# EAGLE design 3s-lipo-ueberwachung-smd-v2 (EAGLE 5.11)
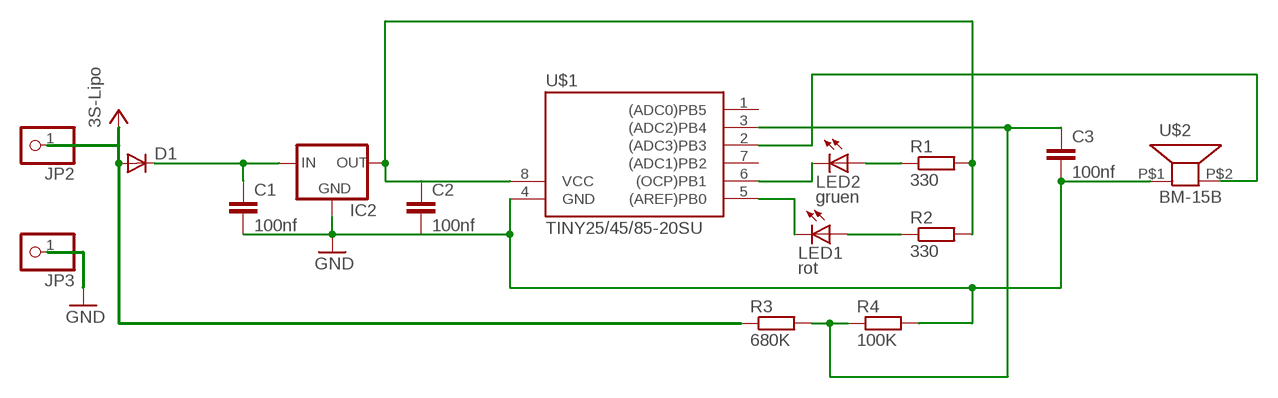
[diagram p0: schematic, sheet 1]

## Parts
C1  100nf  C-EUC0603  [C0603]
C2  100nf  C-EUC0603  [C0603]
C3  100nf  C-EUC0603  [C0603]
D1  DIODE-MINIMELF  [MINIMELF]
IC2  78LXX  [78LXX]
JP2  PINHD-1X1  [1X01]
JP3  PINHD-1X1  [1X01]
LED1  rot  LED3MM  [LED3MM]
LED2  gruen  LED3MM  [LED3MM]
R1  330  R-EU_R0603  [R0603]
R2  330  R-EU_R0603  [R0603]
R3  680K  R-EU_R0603  [R0603]
R4  100K  R-EU_R0603  [R0603]
U$1  TINY25/45/85-20SU  [SOIC8]
U$2  BM-15B  [BM-15B]

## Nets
GND: C1.2 C2.2 C3.2 IC2.GND JP3.1 R4.2 U$1.4(GND) U$2.P$1
N$1: LED2.K(C) U$1.6((OCP)PB1)
N$2: U$1.2((ADC3)PB3) U$2.P$2
N$4: LED1.K(C) U$1.5((AREF)PB0)
N$5: LED2.A R1.1
N$6: LED1.A R2.1
N$7: C1.1 D1.C IC2.IN
N$8: C2.1 IC2.OUT R1.2 R2.2 U$1.8(VCC)
N$9: C3.1 R3.2 R4.1 U$1.3((ADC2)PB4)
VCC: D1.A JP2.1 R3.1 ; supply symbol labelled 3S-Lipo
Unconnected: U$1.1((ADC0)PB5) U$1.7((ADC1)PB2)

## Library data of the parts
C1-C3 = rcl:C-EU: CAPACITOR, European symbol
D1 = diode:DIODE-: DIODE
IC2 = v-reg:78LXX: VOLTAGE REGULATOR
JP2 JP3 = pinhead:PINHD-1X1: PIN HEADER
LED1 LED2 = led:LED: LED
R1-R4 = rcl:R-EU_: RESISTOR, European symbol
U$1 = avr-6:TINY25/45/85
U$2 = buzzer:BM-15B

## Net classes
0 default: width 0.381 mm, clearance 0.381 mm

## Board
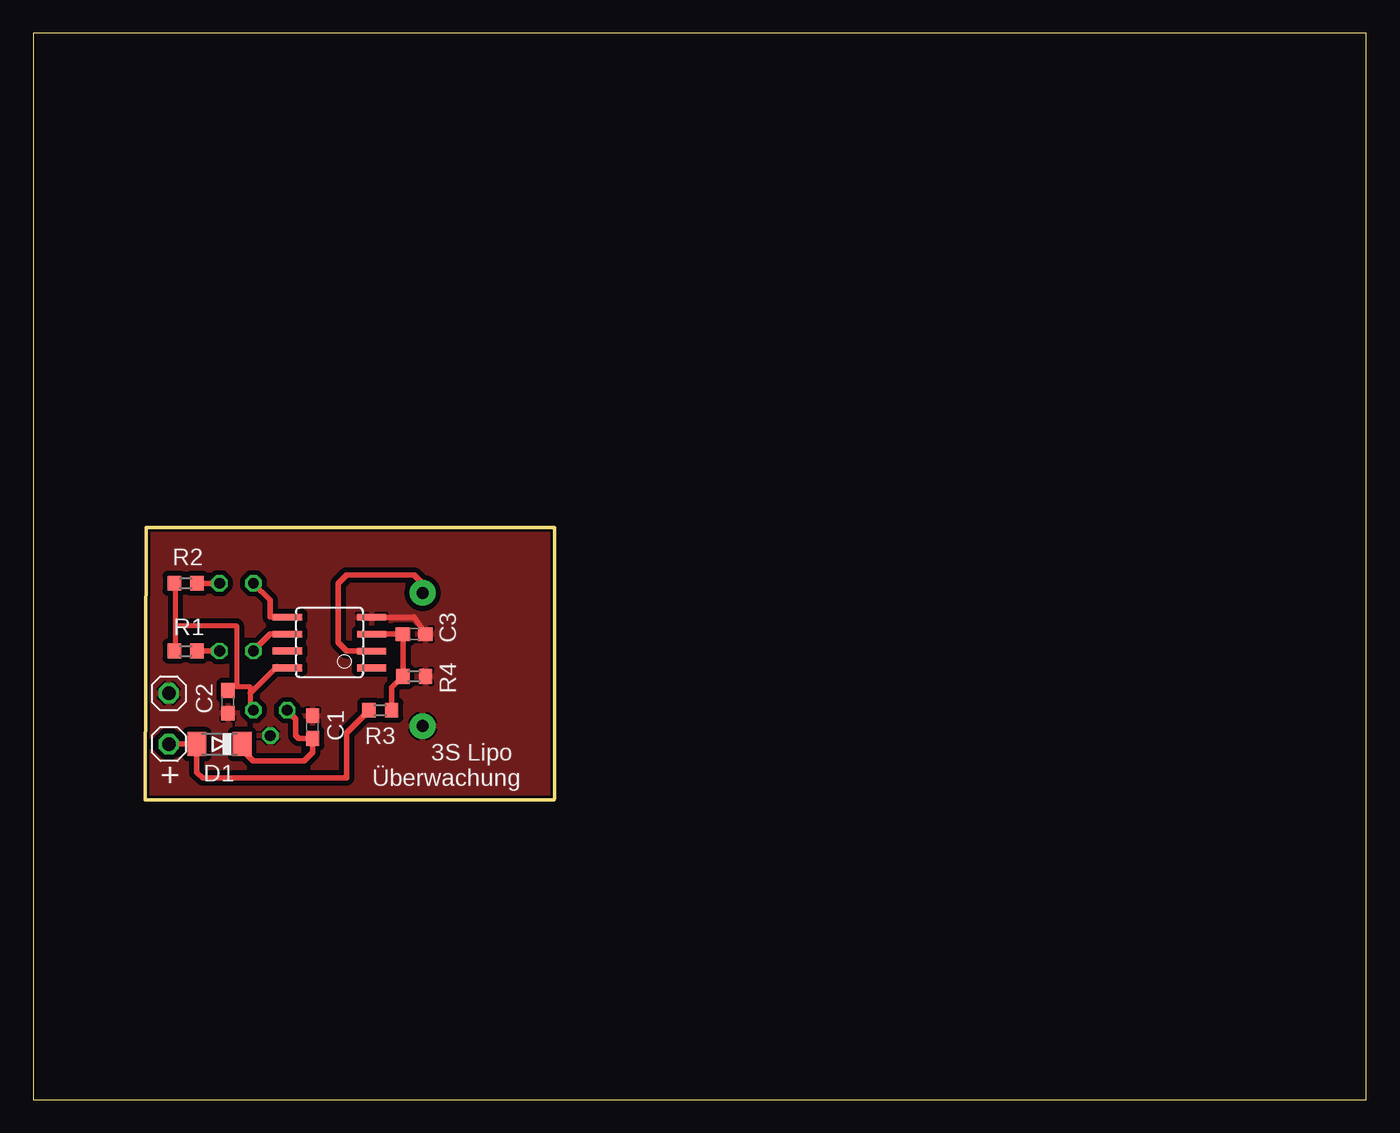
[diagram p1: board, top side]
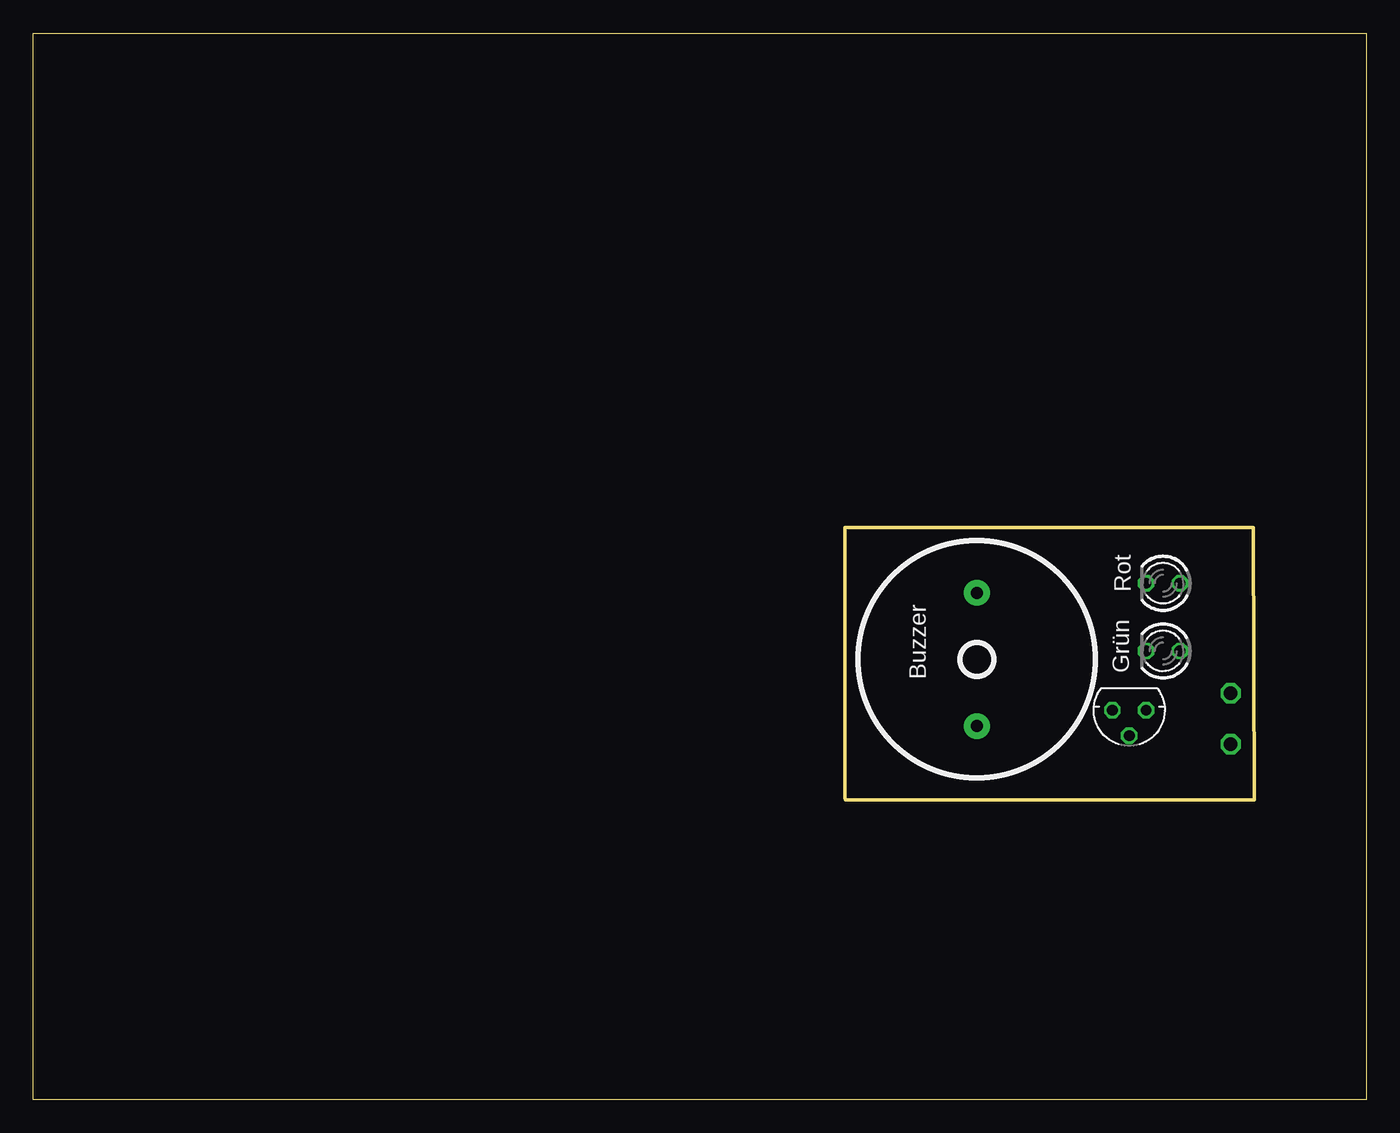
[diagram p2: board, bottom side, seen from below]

Size 100 x 80 mm. Coordinates in mm from the lower left corner, seen from the top.
Outline: 39.07,22.48 8.4,22.49 8.45,42.91 39.12,42.92 39.12,22.61
Outline: 0,0 100,0 100,80 0,80 0,0
Copper layers (1*16): Top 0.035mm / dielectric 1.5mm / Bottom 0.035mm
Design rules "platinensammler_02": minimum track width 0.15mm, minimum drill 0.3mm, track to track 0.15mm, track to pad 0.15mm, pad to pad 0.15mm, via to via 0.15mm, smd to smd 0mil, copper to edge 0.2mm, drill to drill 0.2mm, minimum pad ring 0.2mm, minimum via ring 0.2mm, stop-mask expansion 4mil, vias tented up to drill 0.8mm, thermal gap 0.15mm

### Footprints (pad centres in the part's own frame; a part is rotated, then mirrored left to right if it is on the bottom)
C0603 = smd 1.1 x 1: 1 -0.85,0; 2 0.85,0
MINIMELF = smd 1.4 x 1.8: A 1.7,0; C -1.7,0
78LXX = drill 0.813 octagon: GND 0,1.905; IN 1.27,0; OUT -1.27,0
1X01 = drill 1.016 octagon: 1 0,0
LED3MM = drill 0.813 octagon: A -1.27,0; K 1.27,0
R0603 = smd 1 x 1.1: 1 -0.85,0; 2 0.85,0
SOIC8 = smd 0.5 x 2.2: 1 -1.905,-3.154; 2 -0.645,-3.154; 3 0.625,-3.154; 4 1.895,-3.154; 5 1.905,3.154; 6 0.635,3.154; 7 -0.635,3.154; 8 -1.905,3.154
BM-15B = drill 0.9 pad 1.93 round: P$1 5,0; P$2 -5,0

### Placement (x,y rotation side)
C1  20.95,27.94 90 top
C2  14.61,29.84 270 top
C3  28.57,34.92 0 top
D1  13.97,26.67 180 top
IC2  17.78,29.21 180 bottom
JP2  10.16,26.67 0 top
JP3  10.16,30.48 0 top
LED1  15.24,38.73 180 bottom
LED2  15.24,33.66 180 bottom
R1  11.43,33.66 180 top
R2  11.43,38.73 180 top
R3  26.04,29.21 0 top
R4  28.57,31.75 0 top
U$1  22.23,34.29 90 top
U$2  29.21,33.02 270 bottom

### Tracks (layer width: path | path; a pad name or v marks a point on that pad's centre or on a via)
GND
  Top 0.406: R4.2 29.21,32.17 | U$1.4 28.57,36.19 28.57,36.2 C3.2
  pour Top: 8.89,42.55 38.73,42.55 38.73,22.86 8.89,22.86
N$1
  Top 0.406: U$1.6 17.78,34.92 LED2.K
N$2
  Top 0.406: U$2.P$2 29.21,38.73 28.57,39.37 23.5,39.37 22.86,38.73 22.86,34.29 23.5,33.66 25.37,33.66 U$1.2
N$4
  Top 0.406: U$1.5 17.78,36.2 17.78,37.47 LED1.K
N$5
  Top 0.406: R1.1 LED2.A
N$6
  Top 0.406: R2.1 LED1.A
N$7
  Top 0.406: D1.C 15.67,26.24 16.51,25.4 20.32,25.4 20.95,26.04 C1.1 19.9,27.09 19.68,27.3 19.68,28.57 IC2.IN
N$8
  Top 0.381: 10.67,35.56 10.67,38.61 R2.2 | 10.67,35.56 10.67,34.04 R1.2 | 15.24,30.99 16.26,30.99 16.26,30.48 | 15.24,30.99 14.73,30.99 C2.1 | 16.26,30.48 16.26,29.46 IC2.OUT | 16.26,30.48 18.29,32.51 U$1.8 | 10.67,35.56 15.24,35.56 15.24,30.99
N$9
  Top 0.406: U$1.3 25.39,34.92 C3.1 R4.1 26.89,30.91 R3.2
VCC
  Top 0.406: JP2.1 D1.A 12.27,24.56 12.7,24.13 23.5,24.13 23.5,27.52 R3.1

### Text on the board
tNames: C1 | 3S Lipo | + | Überwachung
bNames: Rot | Buzzer | Grün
